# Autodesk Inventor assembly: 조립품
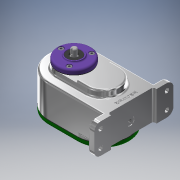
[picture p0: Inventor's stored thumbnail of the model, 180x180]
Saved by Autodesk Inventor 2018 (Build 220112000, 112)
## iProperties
Created: 2021-05
Part Number: 조립품
Material: 일반
Document SubType Name: Assembly
Designer: Admin
Author: Admin
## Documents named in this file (19)
- C:\Users\Admin\Documents\Inventor\710509V1009\조립품.iam
- C:\Users\Admin\Documents\Inventor\710509V1009\본체.ipt
- C:\Users\Admin\Desktop\710509V1009\베어링 6001.ipt
- 베어링 6001.ipt
- C:\Users\Admin\Desktop\710509V1009\베어링 6002.ipt
- 베어링 6002.ipt
- C:\Users\Admin\Desktop\710509V1009\볼트 M4.ipt
- C:\Users\Admin\Desktop\710509V1009\스퍼기어 A.ipt
- C:\Users\Admin\Desktop\710509V1009\스퍼기어 B.ipt
- C:\Users\Admin\Desktop\710509V1009\오일 실 12 22 7.ipt
- C:\Users\Admin\Desktop\710509V1009\축 A.ipt
- C:\Users\Admin\Desktop\710509V1009\축 B.ipt
- C:\Users\Admin\Desktop\710509V1009\칼라.ipt
- C:\Users\Admin\Desktop\710509V1009\커버 A.ipt
- C:\Users\Admin\Desktop\710509V1009\커버 B.ipt
- C:\Users\Admin\Desktop\710509V1009\키 4 x 4 x 12.ipt
- C:\Users\Admin\Desktop\710509V1009\키 5 x 5 x 12.ipt
- C:\Users\Admin\Desktop\710509V1009\개스킷 A.ipt
- C:\Users\Admin\Desktop\710509V1009\개스킷 B.ipt
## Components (2 placed, 2 different names)
1. 개스킷 A:1
2. 개스킷 B:1
